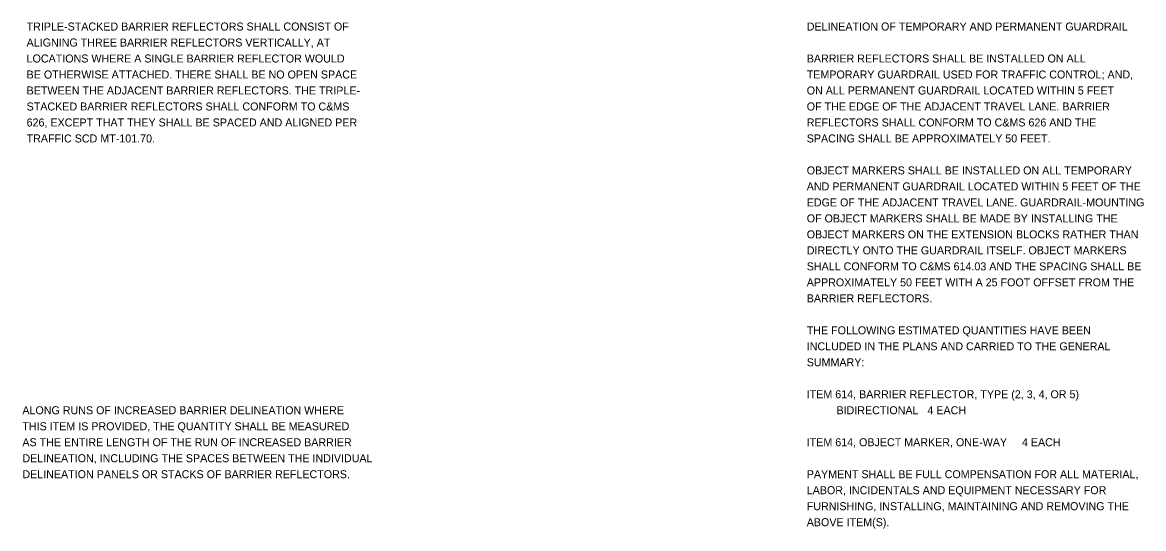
# Model space of a CAD drawing. Extents: x 0 to 83.7, y 0 to 22.
# Drawn here: x 64.05 to 83.67, y 12.28 to 21.14 of the extents above; entities that cross this region are included whole.
import ezdxf

# ---------------------------------------------------------------- set-up
doc = ezdxf.new("R2010")
doc.units = 0
doc.layers.add('SH_Text', color=7, linetype='Continuous')

msp = doc.modelspace()

# ---------------------------------------------------------------- texts
at = {"layer": 'SH_Text'}
for s, p in [('TRIPLE-STACKED BARRIER REFLECTORS SHALL CONSIST OF', (64.119, 21)), ('DELINEATION OF TEMPORARY AND PERMANENT GUARDRAIL', (77.771, 21)), ('ALIGNING THREE BARRIER REFLECTORS VERTICALLY, AT', (64.119, 20.72)), ('LOCATIONS WHERE A SINGLE BARRIER REFLECTOR WOULD', (64.119, 20.44)), ('BARRIER REFLECTORS SHALL BE INSTALLED ON ALL', (77.771, 20.44)), ('BE OTHERWISE ATTACHED. THERE SHALL BE NO OPEN SPACE', (64.119, 20.16)), ('TEMPORARY GUARDRAIL USED FOR TRAFFIC CONTROL; AND,', (77.771, 20.16)), ('BETWEEN THE ADJACENT BARRIER REFLECTORS. THE TRIPLE-', (64.119, 19.88)), ('ON ALL PERMANENT GUARDRAIL LOCATED WITHIN 5 FEET', (77.771, 19.88)), ('STACKED BARRIER REFLECTORS SHALL CONFORM TO C&MS', (64.119, 19.6)), ('OF THE EDGE OF THE ADJACENT TRAVEL LANE. BARRIER', (77.771, 19.6)), ('626, EXCEPT THAT THEY SHALL BE SPACED AND ALIGNED PER', (64.119, 19.32)), ('REFLECTORS SHALL CONFORM TO C&MS 626 AND THE', (77.771, 19.32)), ('TRAFFIC SCD MT-101.70.', (64.119, 19.04)), ('SPACING SHALL BE APPROXIMATELY 50 FEET.', (77.771, 19.04)), ('OBJECT MARKERS SHALL BE INSTALLED ON ALL TEMPORARY', (77.771, 18.48)), ('AND PERMANENT GUARDRAIL LOCATED WITHIN 5 FEET OF THE', (77.771, 18.2)), ('EDGE OF THE ADJACENT TRAVEL LANE. GUARDRAIL-MOUNTING', (77.771, 17.92)), ('OF OBJECT MARKERS SHALL BE MADE BY INSTALLING THE', (77.771, 17.64)), ('OBJECT MARKERS ON THE EXTENSION BLOCKS RATHER THAN', (77.771, 17.36)), ('DIRECTLY ONTO THE GUARDRAIL ITSELF. OBJECT MARKERS', (77.771, 17.08)), ('SHALL CONFORM TO C&MS 614.03 AND THE SPACING SHALL BE', (77.771, 16.8)), ('APPROXIMATELY 50 FEET WITH A 25 FOOT OFFSET FROM THE', (77.771, 16.52)), ('BARRIER REFLECTORS.', (77.771, 16.24)), ('THE FOLLOWING ESTIMATED QUANTITIES HAVE BEEN', (77.771, 15.68)), ('INCLUDED IN THE PLANS AND CARRIED TO THE GENERAL', (77.771, 15.4)), ('SUMMARY:', (77.771, 15.12)), ('ITEM 614, BARRIER REFLECTOR, TYPE (2, 3, 4, OR 5)', (77.771, 14.56)), ('ALONG RUNS OF INCREASED BARRIER DELINEATION WHERE', (64.045, 14.28)), ('          BIDIRECTIONAL   4 EACH', (77.771, 14.28)), ('THIS ITEM IS PROVIDED, THE QUANTITY SHALL BE MEASURED', (64.045, 14)), ('AS THE ENTIRE LENGTH OF THE RUN OF INCREASED BARRIER', (64.045, 13.72)), ('ITEM 614, OBJECT MARKER, ONE-WAY     4 EACH', (77.771, 13.72)), ('DELINEATION, INCLUDING THE SPACES BETWEEN THE INDIVIDUAL', (64.045, 13.44)), ('DELINEATION PANELS OR STACKS OF BARRIER REFLECTORS.', (64.045, 13.16)), ('PAYMENT SHALL BE FULL COMPENSATION FOR ALL MATERIAL,', (77.771, 13.16)), ('LABOR, INCIDENTALS AND EQUIPMENT NECESSARY FOR', (77.771, 12.88)), ('FURNISHING, INSTALLING, MAINTAINING AND REMOVING THE', (77.771, 12.6)), ('ABOVE ITEM(S).', (77.771, 12.32))]:
    msp.add_text(s, height=0.14, dxfattribs=at).set_placement(p)

doc.saveas('drawing.dxf')
